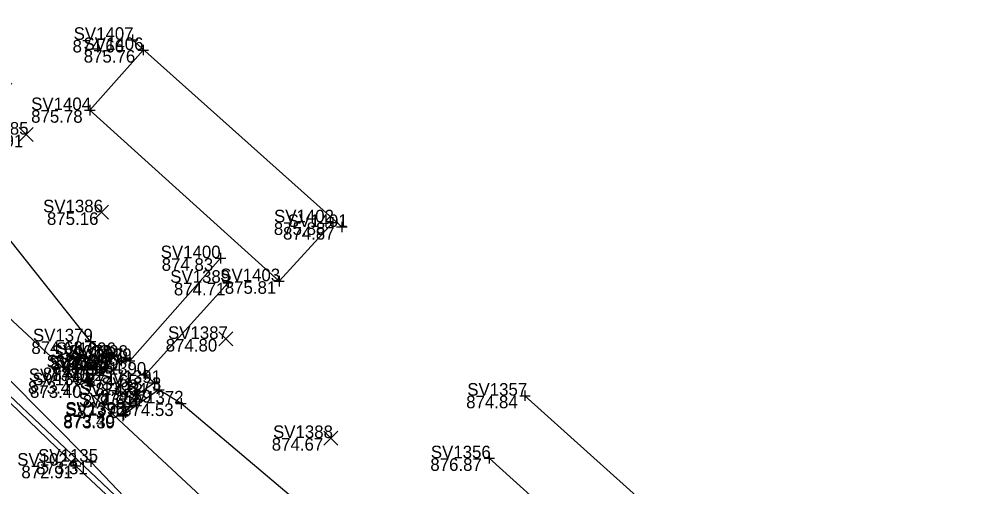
# Model space of a CAD drawing. Extents: x 1480001 to 1480402, y 379235 to 379603.
# Drawn here: x 1480133.3 to 1480223.3, y 379481.8 to 379526.3 of the extents above; entities that cross this region are included whole.
import ezdxf

# ---------------------------------------------------------------- set-up
doc = ezdxf.new("R2010")
doc.units = 0
for name, color, linetype in [('BD_X_Building', 7, 'Continuous'), ('BD_X_Porch_or_Deck', 7, 'Continuous'), ('PV_X_Curb', 7, 'Continuous'), ('PV_X_Walk', 7, 'Continuous'), ('SV_X_Random_Point', 7, 'Continuous'), ('SV_X_Shot_Marker', 7, 'Continuous'), ('SV_X_Text_Elevation', 7, 'Continuous'), ('SV_X_Text_Name', 7, 'Continuous'), ('SV_X_Top_of_Bank', 7, 'Continuous'), ('UT_X_Water', 7, 'Continuous')]:
    doc.layers.add(name, color=color, linetype=linetype)

msp = doc.modelspace()

# ---------------------------------------------------------------- linework, layer by layer
at = {"layer": 'BD_X_Building'}
for p, q in [((1480164.096, 379506.456), (1480144.131, 379524.291)), ((1480194.12, 379479.058), (1480181.546, 379490.377))]:
    msp.add_line(p, q, dxfattribs=at)
at = {"layer": 'BD_X_Porch_or_Deck'}
msp.add_line((1480188.477, 379475.121), (1480178.147, 379484.41), dxfattribs=at)
msp.add_lwpolyline([(1480163.22, 379506.895), (1480158.103, 379501.287), (1480140.07, 379517.594), (1480145.147, 379523.325)], dxfattribs=at)
at = {"layer": 'PV_X_Curb'}
for points in [[(1480042.95, 379573.802), (1480051.182, 379566.018), (1480067.383, 379550.834), (1480087.586, 379531.809), (1480105.067, 379515.41), (1480105.589, 379514.887), (1480115.079, 379506.297), (1480116.303, 379505.052), (1480118.53, 379502.967), (1480120.902, 379500.821), (1480138.714, 379483.703), (1480170.84, 379453.681), (1480172.574, 379452.083), (1480181.867, 379443.345), (1480182.839, 379442.217), (1480185.607, 379439.661), (1480186.493, 379438.955), (1480206.919, 379419.855)], [(1480043.308, 379574.086), (1480051.435, 379566.534), (1480067.64, 379551.083), (1480087.827, 379532.141), (1480105.189, 379515.816), (1480105.937, 379515.205), (1480115.287, 379506.588), (1480116.588, 379505.377), (1480116.999, 379505.563), (1480121.373, 379501.34), (1480121.053, 379501.135), (1480146.64, 379476.909), (1480171.177, 379454.102), (1480173.021, 379452.229), (1480182.175, 379443.675), (1480183.379, 379442.683), (1480186.184, 379440.013), (1480186.975, 379439.363), (1480207.407, 379420.301)]]:
    msp.add_lwpolyline(points, dxfattribs=at)
at = {"layer": 'PV_X_Walk'}
for points in [[(1480235.613, 379401.335), (1480215.341, 379421.047), (1480197.466, 379437.463), (1480177.803, 379455.97), (1480154.79, 379476.967), (1480132.747, 379497.48), (1480113.376, 379516.728), (1480110.754, 379519.04), (1480109.877, 379518.336), (1480091.944, 379535.267), (1480093.027, 379536.619), (1480090.219, 379539.243), (1480090.463, 379539.725), (1480084.681, 379544.882), (1480083.843, 379544.144), (1480066.818, 379560.524), (1480045.662, 379580.046)], [(1480140.103, 379491.371), (1480141.696, 379492.981), (1480142.433, 379494.261), (1480143.057, 379493.677), (1480143.514, 379493.991), (1480143.87, 379493.684), (1480152.532, 379503.479)], [(1480153.241, 379501.138), (1480145.352, 379492.379), (1480146.223, 379491.6), (1480144.597, 379490.448), (1480143.265, 379488.564)]]:
    msp.add_lwpolyline(points, dxfattribs=at)
at = {"layer": 'SV_X_Random_Point'}
for p, q in [((1480133.349, 379514.59), (1480134.683, 379515.925)), ((1480133.349, 379515.925), (1480134.683, 379514.59)), ((1480140.521, 379507.186), (1480141.855, 379508.521)), ((1480140.521, 379508.521), (1480141.855, 379507.186)), ((1480152.352, 379495.119), (1480153.686, 379496.454)), ((1480152.352, 379496.454), (1480153.686, 379495.119)), ((1480162.374, 379485.671), (1480163.708, 379487.006)), ((1480162.374, 379487.006), (1480163.708, 379485.671))]:
    msp.add_line(p, q, dxfattribs=at)
at = {"layer": 'SV_X_Shot_Marker'}
for p, q in [((1480143.631, 379524.291), (1480144.631, 379524.291)), ((1480144.131, 379524.791), (1480144.131, 379523.791)), ((1480144.131, 379524.291), (1480144.131, 379524.291)), ((1480145.147, 379523.825), (1480145.147, 379522.825)), ((1480144.647, 379523.325), (1480145.647, 379523.325)), ((1480145.147, 379523.325), (1480145.147, 379523.325)), ((1480140.07, 379518.094), (1480140.07, 379517.094)), ((1480139.57, 379517.594), (1480140.57, 379517.594)), ((1480140.07, 379517.594), (1480140.07, 379517.594)), ((1480163.22, 379507.395), (1480163.22, 379506.395)), ((1480162.72, 379506.895), (1480163.72, 379506.895)), ((1480163.22, 379506.895), (1480163.22, 379506.895)), ((1480163.596, 379506.456), (1480164.596, 379506.456)), ((1480164.096, 379506.956), (1480164.096, 379505.956)), ((1480164.096, 379506.456), (1480164.096, 379506.456)), ((1480152.532, 379503.979), (1480152.532, 379502.979)), ((1480152.032, 379503.479), (1480153.032, 379503.479)), ((1480152.532, 379503.479), (1480152.532, 379503.479)), ((1480158.103, 379501.787), (1480158.103, 379500.787)), ((1480152.741, 379501.138), (1480153.741, 379501.138)), ((1480153.241, 379501.638), (1480153.241, 379500.638)), ((1480153.241, 379501.138), (1480153.241, 379501.138)), ((1480157.603, 379501.287), (1480158.603, 379501.287)), ((1480158.103, 379501.287), (1480158.103, 379501.287)), ((1480139.638, 379495.555), (1480140.638, 379495.555)), ((1480140.138, 379496.055), (1480140.138, 379495.055)), ((1480140.138, 379495.555), (1480140.138, 379495.555)), ((1480142.433, 379494.761), (1480142.433, 379493.761)), ((1480141.437, 379493.998), (1480142.437, 379493.998)), ((1480141.933, 379494.261), (1480142.933, 379494.261)), ((1480141.937, 379494.498), (1480141.937, 379493.498)), ((1480141.937, 379493.998), (1480141.937, 379493.998)), ((1480142.433, 379494.261), (1480142.433, 379494.261)), ((1480142.557, 379493.677), (1480143.557, 379493.677)), ((1480143.014, 379493.991), (1480144.014, 379493.991)), ((1480143.057, 379494.177), (1480143.057, 379493.177)), ((1480143.057, 379493.677), (1480143.057, 379493.677)), ((1480143.37, 379493.684), (1480144.37, 379493.684)), ((1480143.514, 379494.491), (1480143.514, 379493.491)), ((1480143.514, 379493.991), (1480143.514, 379493.991)), ((1480143.87, 379494.184), (1480143.87, 379493.184)), ((1480143.87, 379493.684), (1480143.87, 379493.684)), ((1480140.927, 379493.056), (1480141.927, 379493.056)), ((1480141.196, 379492.981), (1480142.196, 379492.981)), ((1480141.427, 379493.556), (1480141.427, 379492.556)), ((1480141.427, 379493.056), (1480141.427, 379493.056)), ((1480141.696, 379493.481), (1480141.696, 379492.481)), ((1480141.696, 379492.981), (1480141.696, 379492.981)), ((1480145.352, 379492.879), (1480145.352, 379491.879)), ((1480139.808, 379492.265), (1480139.808, 379491.265)), ((1480140.103, 379491.871), (1480140.103, 379490.871)), ((1480144.852, 379492.379), (1480145.852, 379492.379)), ((1480145.352, 379492.379), (1480145.352, 379492.379)), ((1480146.223, 379492.1), (1480146.223, 379491.1)), ((1480139.308, 379491.765), (1480140.308, 379491.765)), ((1480139.603, 379491.371), (1480140.603, 379491.371)), ((1480139.808, 379491.765), (1480139.808, 379491.765)), ((1480140.103, 379491.371), (1480140.103, 379491.371)), ((1480144.597, 379490.948), (1480144.597, 379489.948)), ((1480145.723, 379491.6), (1480146.723, 379491.6)), ((1480146.223, 379491.6), (1480146.223, 379491.6)), ((1480146.649, 379491.426), (1480146.649, 379490.426)), ((1480144.097, 379490.448), (1480145.097, 379490.448)), ((1480144.597, 379490.448), (1480144.597, 379490.448)), ((1480146.149, 379490.926), (1480147.149, 379490.926)), ((1480146.649, 379490.926), (1480146.649, 379490.926)), ((1480148.764, 379490.138), (1480148.764, 379489.138)), ((1480181.046, 379490.377), (1480182.046, 379490.377)), ((1480181.546, 379490.877), (1480181.546, 379489.877)), ((1480181.546, 379490.377), (1480181.546, 379490.377)), ((1480143.983, 379489.446), (1480144.983, 379489.446)), ((1480144.483, 379489.946), (1480144.483, 379488.946)), ((1480144.483, 379489.446), (1480144.483, 379489.446)), ((1480148.264, 379489.638), (1480149.264, 379489.638)), ((1480148.764, 379489.638), (1480148.764, 379489.638)), ((1480142.712, 379488.463), (1480143.712, 379488.463)), ((1480142.765, 379488.564), (1480143.765, 379488.564)), ((1480143.212, 379488.963), (1480143.212, 379487.963)), ((1480143.212, 379488.463), (1480143.212, 379488.463)), ((1480143.265, 379489.064), (1480143.265, 379488.064)), ((1480143.265, 379488.564), (1480143.265, 379488.564)), ((1480178.147, 379484.91), (1480178.147, 379483.91)), ((1480138.714, 379484.203), (1480138.714, 379483.203)), ((1480139.666, 379484.084), (1480140.666, 379484.084)), ((1480140.166, 379484.584), (1480140.166, 379483.584)), ((1480140.166, 379484.084), (1480140.166, 379484.084)), ((1480177.647, 379484.41), (1480178.647, 379484.41)), ((1480178.147, 379484.41), (1480178.147, 379484.41)), ((1480138.214, 379483.703), (1480139.214, 379483.703)), ((1480138.714, 379483.703), (1480138.714, 379483.703))]:
    msp.add_line(p, q, dxfattribs=at)
at = {"layer": 'SV_X_Top_of_Bank'}
for points in [[(1480139.808, 379491.765), (1480141.427, 379493.056), (1480141.937, 379493.998), (1480140.138, 379495.555), (1480131.076, 379506.913), (1480127.878, 379509.549), (1480127.257, 379513.845), (1480127.148, 379513.859), (1480132.645, 379520.158)], [(1480170.345, 379463.114), (1480171.936, 379465.283), (1480168.947, 379471.416), (1480162.966, 379477.627), (1480148.764, 379489.638), (1480146.649, 379490.926), (1480144.483, 379489.446), (1480143.212, 379488.463)]]:
    msp.add_lwpolyline(points, dxfattribs=at)
at = {"layer": 'UT_X_Water'}
msp.add_lwpolyline([(1480049.152, 379568.017), (1480068.611, 379550.193), (1480086.403, 379533.424), (1480090.024, 379530.079), (1480102.295, 379519.134), (1480111.734, 379511.473), (1480120.332, 379509.136), (1480127.535, 379501.668), (1480127.911, 379496.395), (1480140.166, 379484.084), (1480149.088, 379474.708), (1480164.726, 379459.482), (1480172.622, 379452.503), (1480197.813, 379429.111), (1480212.628, 379415.684), (1480231.592, 379398.237)], dxfattribs=at)

# ---------------------------------------------------------------- texts
at = {"layer": 'SV_X_Text_Elevation'}
for s, p in [('874.66', (1480138.424, 379523.091)), ('875.76', (1480139.488, 379522.125)), ('875.78', (1480134.477, 379516.394)), ('874.91', (1480128.819, 379514.058)), ('875.16', (1480135.983, 379506.653)), ('875.88', (1480157.608, 379505.695)), ('874.87', (1480158.484, 379505.256)), ('874.83', (1480146.92, 379502.279)), ('874.71', (1480148.082, 379499.938)), ('875.81', (1480152.934, 379500.087)), ('874.68', (1480134.497, 379494.355)), ('874.80', (1480147.303, 379494.586)), ('874.58', (1480136.315, 379492.798)), ('874.59', (1480136.811, 379493.061)), ('874.65', (1480137.426, 379492.477)), ('874.69', (1480137.873, 379492.791)), ('874.64', (1480138.248, 379492.484)), ('874.00', (1480135.598, 379491.856)), ('874.51', (1480136.518, 379491.781)), ('874.65', (1480139.721, 379491.179)), ('873.47', (1480134.177, 379490.565)), ('873.40', (1480134.368, 379490.171)), ('874.64', (1480140.601, 379490.4)), ('874.59', (1480141.027, 379489.726)), ('874.61', (1480139.4, 379489.248)), ('874.84', (1480175.943, 379489.177)), ('873.94', (1480138.852, 379488.246)), ('874.53', (1480143.152, 379488.438)), ('873.40', (1480137.53, 379487.364)), ('873.39', (1480137.562, 379487.263)), ('874.67', (1480157.41, 379485.138)), ('873.31', (1480134.959, 379482.884)), ('876.87', (1480172.525, 379483.21)), ('872.91', (1480133.545, 379482.503))]:
    msp.add_text(s, height=1.2, dxfattribs=at).set_placement(p)
at = {"layer": 'SV_X_Text_Name'}
for s, p in [('SV1407', (1480138.529, 379524.291)), ('SV1406', (1480139.469, 379523.325)), ('SV1404', (1480134.477, 379517.594)), ('SV1385', (1480128.518, 379515.258)), ('SV1386', (1480135.614, 379507.853)), ('SV1402', (1480157.627, 379506.895)), ('SV1401', (1480158.928, 379506.456)), ('SV1400', (1480146.826, 379503.479)), ('SV1389', (1480147.733, 379501.138)), ('SV1403', (1480152.501, 379501.287)), ('SV1379', (1480134.649, 379495.555)), ('SV1387', (1480147.521, 379495.786)), ('SV1396', (1480136.84, 379494.261)), ('SV1378', (1480136.448, 379493.998)), ('SV1397', (1480137.54, 379493.677)), ('SV1398', (1480137.987, 379493.991)), ('SV1399', (1480138.343, 379493.684)), ('SV1377', (1480135.948, 379493.056)), ('SV1395', (1480136.179, 379492.981)), ('SV1376', (1480134.253, 379491.765)), ('SV1390', (1480139.731, 379492.379)), ('SV1391', (1480141.14, 379491.6)), ('SV1394', (1480134.595, 379491.371)), ('SV1373', (1480141.17, 379490.926)), ('SV1392', (1480139.089, 379490.448)), ('SV1357', (1480176.048, 379490.377)), ('SV1374', (1480139.013, 379489.446)), ('SV1372', (1480143.294, 379489.638)), ('SV1375', (1480137.733, 379488.463)), ('SV1393', (1480137.748, 379488.564)), ('SV1388', (1480157.533, 379486.338)), ('SV1356', (1480172.573, 379484.41)), ('SV1022', (1480133.15, 379483.703)), ('SV1135', (1480135.141, 379484.084))]:
    msp.add_text(s, height=1.2, dxfattribs=at).set_placement(p)

doc.saveas('drawing.dxf')
